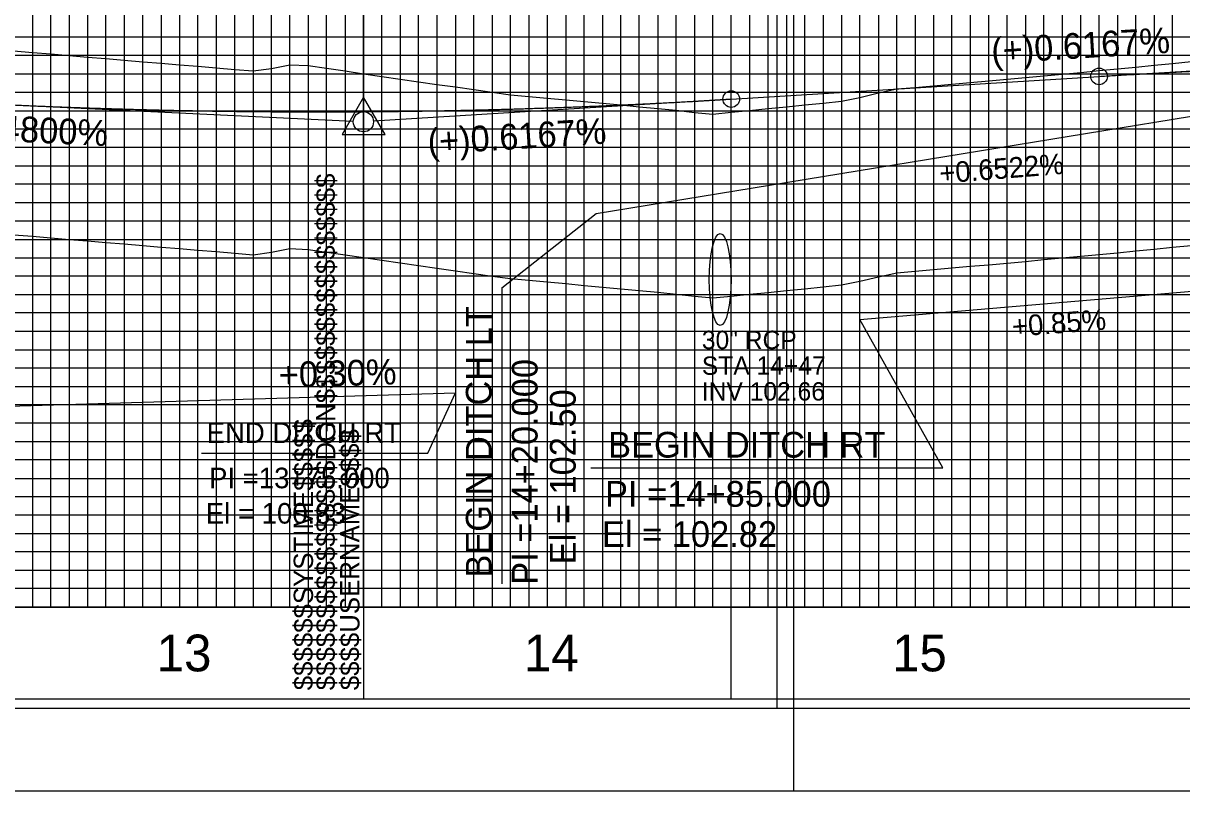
# Model space of a CAD drawing. Extents: x 2345490 to 2436403, y 465165 to 573888.
# Drawn here: x 2412152.8 to 2412467.8, y 527722 to 527930.9 of the extents above; entities that cross this region are included whole.
import ezdxf

# ---------------------------------------------------------------- set-up
doc = ezdxf.new("R2010")
doc.units = 0
for name, color, linetype in [('Old_Level_1', 7, 'Continuous'), ('Old_Level_18', 7, 'Continuous'), ('Old_Level_2', 7, 'Continuous'), ('Old_Level_3', 7, 'Continuous'), ('Old_Level_4', 7, 'Continuous'), ('Old_Level_40', 7, 'Continuous'), ('Old_Level_41', 7, 'Continuous'), ('Old_Level_42', 7, 'Continuous'), ('Old_Level_43', 7, 'Continuous'), ('Old_Level_50', 7, 'Continuous'), ('Old_Level_51', 7, 'Continuous'), ('Old_Level_61', 7, 'Continuous'), ('Old_Level_62', 7, 'Continuous'), ('Old_Level_63', 7, 'Continuous')]:
    doc.layers.add(name, color=color, linetype=linetype)

msp = doc.modelspace()

# ---------------------------------------------------------------- linework, layer by layer
at = {"layer": 'Old_Level_1'}
for points in [[(2412150.325, 527873.32075), (2412155.325, 527872.89975), (2412160.325, 527872.47925), (2412165.325, 527872.059), (2412170.325, 527871.63925), (2412175.325, 527871.22), (2412180.325, 527870.801), (2412185.325, 527870.38225), (2412190.325, 527869.964), (2412195.325, 527869.54625), (2412200.325, 527869.12875), (2412205.325, 527868.7115), (2412210.325, 527868.2945), (2412215.325, 527867.878), (2412220.325, 527868.54175), (2412225.325, 527869.5565), (2412230.325, 527869.31875), (2412235.325, 527868.58475), (2412240.325, 527867.85275), (2412245.325, 527867.1225), (2412250.325, 527866.39425), (2412255.325, 527865.66775), (2412260.325, 527864.94275), (2412265.325, 527864.21925), (2412270.325, 527863.49725), (2412275.325, 527862.77675), (2412280.325, 527862.0575), (2412285.325, 527861.40125), (2412290.325, 527860.93575), (2412295.325, 527860.47025), (2412300.325, 527860.00475), (2412305.325, 527859.5395), (2412310.325, 527859.0745), (2412315.325, 527858.6095), (2412320.325, 527858.1445), (2412325.325, 527857.6795), (2412330.325, 527857.18775), (2412335.325, 527856.59875), (2412340.325, 527856.11425), (2412345.325, 527856.617), (2412350.325, 527857.11975), (2412355.325, 527857.62275), (2412360.325, 527858.12575), (2412365.325, 527858.62925), (2412370.325, 527859.1335), (2412375.325, 527859.6385), (2412380.325, 527860.68375), (2412385.325, 527861.87775), (2412390.325, 527862.97175), (2412395.325, 527863.4045)], [(2412395.325, 527863.4045), (2412400.325, 527863.84), (2412405.325, 527864.27875), (2412410.325, 527864.721), (2412415.325, 527865.167), (2412420.325, 527865.61725), (2412425.325, 527866.07175), (2412430.325, 527866.53125), (2412435.325, 527866.99575), (2412440.325, 527867.4655), (2412445.325, 527867.94075), (2412450.325, 527868.42225), (2412455.325, 527868.91), (2412460.325, 527869.40425), (2412465.325, 527869.9055), (2412470.325, 527870.41375)]]:
    msp.add_lwpolyline(points, dxfattribs=at)
at = {"layer": 'Old_Level_18'}
msp.add_line((2412245.325, 527747.04275), (2412245.325, 527747.04275), dxfattribs=at)
msp.add_line((2412245.325, 527747.04275), (2412245.325, 527747.04275), dxfattribs=at)
for points in [[(2412345.325, 528797.04275), (2410845.325, 528797.04275), (2410845.325, 527747.04275), (2412345.325, 527747.04275)], [(2413745.325, 528797.04275), (2412245.325, 528797.04275), (2412245.325, 527747.04275), (2413745.325, 527747.04275)]]:
    msp.add_lwpolyline(points, close=True, dxfattribs=at)
at = {"layer": 'Old_Level_2'}
for p, q in [((2412445.325, 527916.3765), (2412542.58025, 527922.37375)), ((2412345.325, 527910.20975), (2412445.325, 527916.3765)), ((2412145.325, 527908.843), (2412242.57825, 527904.175)), ((2412345.325, 527910.20975), (2412248.07, 527904.2125))]:
    msp.add_line(p, q, dxfattribs=at)
msp.add_lwpolyline([(2412239.51925, 527900.592), (2412251.26175, 527900.592), (2412245.39075, 527910.71775)], close=True, dxfattribs=at)
for centre, radius in [((2412445.325, 527916.3765), 2.25), ((2412345.325, 527910.20975), 2.25), ((2412245.325, 527904.043), 2.75)]:
    msp.add_circle(centre, radius, dxfattribs=at)
for points in [[(2412445.325, 527916.3765), (2412449.325, 527916.61925), (2412453.325, 527916.85475), (2412457.325, 527917.0825), (2412461.325, 527917.303), (2412465.325, 527917.51575), (2412469.325, 527917.721), (2412473.325, 527917.91875), (2412477.325, 527918.109), (2412481.325, 527918.29175), (2412485.325, 527918.467), (2412489.325, 527918.63475), (2412493.325, 527918.79475), (2412497.325, 527918.9475), (2412501.325, 527919.0925), (2412505.325, 527919.23025), (2412509.325, 527919.36025), (2412513.325, 527919.48275), (2412517.325, 527919.59775), (2412521.325, 527919.70525), (2412525.325, 527919.80525), (2412529.325, 527919.89775), (2412533.325, 527919.98275), (2412537.325, 527920.06), (2412541.325, 527920.13), (2412545.325, 527920.19225), (2412549.325, 527920.24725), (2412553.325, 527920.2945), (2412557.325, 527920.33425), (2412561.325, 527920.3665), (2412565.325, 527920.39125), (2412569.325, 527920.4085), (2412573.325, 527920.41825), (2412577.325, 527920.4205), (2412581.325, 527920.41525), (2412585.325, 527920.40225), (2412589.325, 527920.382), (2412593.325, 527920.354), (2412597.325, 527920.3185), (2412601.325, 527920.27575), (2412605.325, 527920.22525), (2412609.325, 527920.16725), (2412613.325, 527920.10175), (2412617.325, 527920.02875), (2412621.325, 527919.948), (2412625.325, 527919.86), (2412629.325, 527919.7645), (2412633.325, 527919.66125), (2412637.325, 527919.55075), (2412641.325, 527919.4325), (2412645.325, 527919.30675)], [(2412145.325, 527908.843), (2412149.325, 527908.6555), (2412153.325, 527908.47675), (2412157.325, 527908.3065), (2412161.325, 527908.14525), (2412165.325, 527907.99275), (2412169.325, 527907.849), (2412173.325, 527907.714), (2412177.325, 527907.58775), (2412181.325, 527907.4705), (2412185.325, 527907.36175), (2412189.325, 527907.262), (2412193.325, 527907.17075), (2412197.325, 527907.0885), (2412201.325, 527907.015), (2412205.325, 527906.95), (2412209.325, 527906.894), (2412213.325, 527906.84675), (2412217.325, 527906.8085), (2412221.325, 527906.77875), (2412225.325, 527906.75775), (2412229.325, 527906.74575), (2412233.325, 527906.74225), (2412237.325, 527906.74775), (2412241.325, 527906.76175), (2412245.325, 527906.78475), (2412249.325, 527906.8165), (2412253.325, 527906.857), (2412257.325, 527906.90625), (2412261.325, 527906.96425), (2412265.325, 527907.031), (2412269.325, 527907.10675), (2412273.325, 527907.191), (2412277.325, 527907.28425), (2412281.325, 527907.386), (2412285.325, 527907.49675), (2412289.325, 527907.61625), (2412293.325, 527907.7445), (2412297.325, 527907.8815), (2412301.325, 527908.02725), (2412305.325, 527908.18175), (2412309.325, 527908.345), (2412313.325, 527908.51725), (2412317.325, 527908.698), (2412321.325, 527908.88775), (2412325.325, 527909.086), (2412329.325, 527909.29325), (2412333.325, 527909.50925), (2412337.325, 527909.734), (2412341.325, 527909.9675), (2412345.325, 527910.20975)]]:
    msp.add_spline(points, degree=3, dxfattribs=at)
at = {"layer": 'Old_Level_3'}
for p, q in [((2412308.63157, 527879.04516), (2412552.93924, 527919.02289)), ((2412282.97387, 527858.8775), (2412308.63157, 527879.04516)), ((2412282.97387, 527858.8775), (2412282.97387, 527778.33025)), ((2412380.325, 527850.24275), (2412495.325, 527860.04275)), ((2412402.87748, 527809.87907), (2412380.325, 527850.24275)), ((2411895.325, 527819.04275), (2412270.325, 527830.34275)), ((2412262.87798, 527813.9032), (2412270.325, 527830.34275)), ((2412201.33093, 527813.9032), (2412262.87798, 527813.9032)), ((2412307.11146, 527809.87907), (2412402.87748, 527809.87907))]:
    msp.add_line(p, q, dxfattribs=at)
at = {"layer": 'Old_Level_4'}
msp.add_ellipse((2412342.325, 527861.14275), major_axis=(0, 12.5), ratio=0.238746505, dxfattribs=at)
at = {"layer": 'Old_Level_40'}
msp.add_line((2412245.325, 527747.04275), (2412245.325, 527747.04275), dxfattribs=at)
msp.add_line((2412245.325, 527747.04275), (2412245.325, 527747.04275), dxfattribs=at)
msp.add_line((2412245.325, 527747.04275), (2412245.325, 527747.04275), dxfattribs=at)
msp.add_line((2412245.325, 527747.04275), (2412245.325, 527747.04275), dxfattribs=at)
at = {"layer": 'Old_Level_41'}
for p, q in [((2412345.325, 527772.04275), (2410845.325, 527772.04275)), ((2413745.325, 527772.04275), (2412245.325, 527772.04275))]:
    msp.add_line(p, q, dxfattribs=at)
for points in [[(2412295.325, 528797.04275), (2412295.325, 527772.04275), (2412345.325, 527772.04275), (2412345.325, 528797.04275)], [(2412320.325, 527772.04275), (2412320.325, 528797.04275)], [(2412370.325, 528797.04275), (2412370.325, 527772.04275), (2412420.325, 527772.04275), (2412420.325, 528797.04275)], [(2412395.325, 528797.04275), (2412395.325, 527772.04275), (2412445.325, 527772.04275), (2412445.325, 528797.04275)], [(2412170.325, 528659.49275), (2412170.325, 527772.04275), (2412220.325, 527772.04275), (2412220.325, 528659.49275)], [(2412270.325, 528659.49275), (2412270.325, 527772.04275)], [(2412345.325, 527897.04275), (2410845.325, 527897.04275), (2410845.325, 527847.04275), (2412345.325, 527847.04275)], [(2413745.325, 527897.04275), (2412245.325, 527897.04275), (2412245.325, 527847.04275), (2413745.325, 527847.04275)], [(2412345.325, 527822.04275), (2410845.325, 527822.04275), (2410845.325, 527872.04275), (2412345.325, 527872.04275)], [(2413745.325, 527822.04275), (2412245.325, 527822.04275), (2412245.325, 527872.04275), (2413745.325, 527872.04275)], [(2412345.325, 527797.04275), (2410845.325, 527797.04275)], [(2413745.325, 527797.04275), (2412245.325, 527797.04275)], [(2412282.825, 527747.04275), (2412282.825, 527747.04275)]]:
    msp.add_lwpolyline(points, dxfattribs=at)
at = {"layer": 'Old_Level_42'}
for points in [[(2412195.325, 528659.49275), (2412195.325, 527772.04275), (2412245.325, 527772.04275), (2412245.325, 528659.49275)], [(2412295.325, 528659.49275), (2412295.325, 527772.04275), (2412345.325, 527772.04275)], [(2412345.325, 527922.04275), (2410845.325, 527922.04275), (2410845.325, 527972.04275), (2412345.325, 527972.04275)], [(2413745.325, 527922.04275), (2412245.325, 527922.04275), (2412245.325, 527972.04275), (2413745.325, 527972.04275)]]:
    msp.add_lwpolyline(points, dxfattribs=at)
at = {"layer": 'Old_Level_43'}
for points in [[(2412300.325, 528797.04275), (2412300.325, 527772.04275), (2412305.325, 527772.04275), (2412305.325, 528797.04275)], [(2412310.325, 528797.04275), (2412310.325, 527772.04275), (2412315.325, 527772.04275), (2412315.325, 528797.04275)], [(2412325.325, 528797.04275), (2412325.325, 527772.04275), (2412330.325, 527772.04275), (2412330.325, 528797.04275)], [(2412335.325, 528797.04275), (2412335.325, 527772.04275), (2412340.325, 527772.04275), (2412340.325, 528797.04275)], [(2412350.325, 528797.04275), (2412350.325, 527772.04275), (2412355.325, 527772.04275), (2412355.325, 528797.04275)], [(2412360.325, 528797.04275), (2412360.325, 527772.04275), (2412365.325, 527772.04275), (2412365.325, 528797.04275)], [(2412375.325, 528797.04275), (2412375.325, 527772.04275), (2412380.325, 527772.04275), (2412380.325, 528797.04275)], [(2412385.325, 528797.04275), (2412385.325, 527772.04275), (2412390.325, 527772.04275), (2412390.325, 528797.04275)], [(2412400.325, 528797.04275), (2412400.325, 527772.04275), (2412405.325, 527772.04275), (2412405.325, 528797.04275)], [(2412410.325, 528797.04275), (2412410.325, 527772.04275), (2412415.325, 527772.04275), (2412415.325, 528797.04275)], [(2412425.325, 528797.04275), (2412425.325, 527772.04275), (2412430.325, 527772.04275), (2412430.325, 528797.04275)], [(2412435.325, 528797.04275), (2412435.325, 527772.04275), (2412440.325, 527772.04275), (2412440.325, 528797.04275)], [(2412450.325, 528797.04275), (2412450.325, 527772.04275), (2412455.325, 527772.04275), (2412455.325, 528797.04275)], [(2412460.325, 527772.04275), (2412465.325, 527772.04275), (2412465.325, 528797.04275)], [(2412460.325, 528797.04275), (2412460.325, 527772.04275)], [(2412155.325, 528659.49275), (2412155.325, 527772.04275), (2412160.325, 527772.04275), (2412160.325, 528659.49275)], [(2412165.325, 528659.49275), (2412165.325, 527772.04275), (2412175.325, 527772.04275), (2412175.325, 528659.49275)], [(2412180.325, 528659.49275), (2412180.325, 527772.04275), (2412185.325, 527772.04275), (2412185.325, 528659.49275)], [(2412190.325, 528659.49275), (2412190.325, 527772.04275), (2412200.325, 527772.04275), (2412200.325, 528659.49275)], [(2412205.325, 528659.49275), (2412205.325, 527772.04275), (2412210.325, 527772.04275), (2412210.325, 528659.49275)], [(2412215.325, 528659.49275), (2412215.325, 527772.04275), (2412225.325, 527772.04275), (2412225.325, 528659.49275)], [(2412230.325, 528659.49275), (2412230.325, 527772.04275)], [(2412230.325, 527772.04275), (2412235.325, 527772.04275), (2412235.325, 528659.49275)], [(2412240.325, 528659.49275), (2412240.325, 527772.04275), (2412250.325, 527772.04275), (2412250.325, 528659.49275)], [(2412255.325, 528659.49275), (2412255.325, 527772.04275), (2412260.325, 527772.04275), (2412260.325, 528659.49275)], [(2412265.325, 528659.49275), (2412265.325, 527772.04275), (2412275.325, 527772.04275), (2412275.325, 528659.49275)], [(2412280.325, 528659.49275), (2412280.325, 527772.04275), (2412285.325, 527772.04275), (2412285.325, 528659.49275)], [(2412290.325, 528659.49275), (2412290.325, 527772.04275), (2412300.325, 527772.04275)], [(2412295.325, 527927.04275), (2410895.325, 527927.04275), (2410895.325, 527917.04275), (2412295.325, 527917.04275)], [(2413695.325, 527927.04275), (2412295.325, 527927.04275), (2412295.325, 527917.04275), (2413695.325, 527917.04275)], [(2412295.325, 527912.04275), (2410895.325, 527912.04275), (2410895.325, 527907.04275), (2412295.325, 527907.04275)], [(2413695.325, 527912.04275), (2412295.325, 527912.04275), (2412295.325, 527907.04275), (2413695.325, 527907.04275)], [(2412295.325, 527902.04275), (2410895.325, 527902.04275), (2410895.325, 527892.04275), (2412295.325, 527892.04275)], [(2413695.325, 527902.04275), (2412295.325, 527902.04275), (2412295.325, 527892.04275), (2413695.325, 527892.04275)], [(2412295.325, 527887.04275), (2410895.325, 527887.04275), (2410895.325, 527882.04275), (2412295.325, 527882.04275)], [(2413695.325, 527887.04275), (2412295.325, 527887.04275), (2412295.325, 527882.04275), (2413695.325, 527882.04275)], [(2412295.325, 527877.04275), (2410895.325, 527877.04275), (2410895.325, 527867.04275), (2412295.325, 527867.04275)], [(2413695.325, 527877.04275), (2412295.325, 527877.04275), (2412295.325, 527867.04275), (2413695.325, 527867.04275)], [(2412295.325, 527862.04275), (2410895.325, 527862.04275), (2410895.325, 527857.04275), (2412295.325, 527857.04275)], [(2413695.325, 527862.04275), (2412295.325, 527862.04275), (2412295.325, 527857.04275), (2413695.325, 527857.04275)], [(2412295.325, 527852.04275), (2410895.325, 527852.04275), (2410895.325, 527842.04275), (2412295.325, 527842.04275)], [(2413695.325, 527852.04275), (2412295.325, 527852.04275), (2412295.325, 527842.04275), (2413695.325, 527842.04275)], [(2412295.325, 527837.04275), (2410895.325, 527837.04275), (2410895.325, 527832.04275), (2412295.325, 527832.04275)], [(2413695.325, 527837.04275), (2412295.325, 527837.04275), (2412295.325, 527832.04275), (2413695.325, 527832.04275)], [(2412295.325, 527827.04275), (2410895.325, 527827.04275), (2410895.325, 527817.04275), (2412295.325, 527817.04275)], [(2413695.325, 527827.04275), (2412295.325, 527827.04275), (2412295.325, 527817.04275), (2413695.325, 527817.04275)], [(2412295.325, 527812.04275), (2410895.325, 527812.04275), (2410895.325, 527807.04275), (2412295.325, 527807.04275)], [(2413695.325, 527812.04275), (2412295.325, 527812.04275), (2412295.325, 527807.04275), (2413695.325, 527807.04275)], [(2412295.325, 527802.04275), (2410895.325, 527802.04275), (2410895.325, 527792.04275), (2412295.325, 527792.04275)], [(2413695.325, 527802.04275), (2412295.325, 527802.04275), (2412295.325, 527792.04275), (2413695.325, 527792.04275)], [(2412295.325, 527787.04275), (2410895.325, 527787.04275), (2410895.325, 527782.04275), (2412295.325, 527782.04275)], [(2413695.325, 527787.04275), (2412295.325, 527787.04275), (2412295.325, 527782.04275), (2413695.325, 527782.04275)], [(2412295.325, 527777.04275), (2410895.325, 527777.04275)], [(2413695.325, 527777.04275), (2412295.325, 527777.04275)]]:
    msp.add_lwpolyline(points, dxfattribs=at)
at = {"layer": 'Old_Level_50'}
for points in [[(2412357.825, 528799.59275), (2410691.325, 528799.59275), (2410691.325, 527744.49275), (2412357.825, 527744.49275)], [(2413757.825, 528799.59275), (2412091.325, 528799.59275), (2412091.325, 527744.49275), (2413757.825, 527744.49275)]]:
    msp.add_lwpolyline(points, close=True, dxfattribs=at)
at = {"layer": 'Old_Level_51'}
for points in [[(2412362.325, 528822.04275), (2410678.325, 528822.04275), (2410678.325, 527722.04275), (2412362.325, 527722.04275)], [(2413762.325, 528822.04275), (2412078.325, 528822.04275), (2412078.325, 527722.04275), (2413762.325, 527722.04275)]]:
    msp.add_lwpolyline(points, close=True, dxfattribs=at)
at = {"layer": 'Old_Level_61'}
msp.add_lwpolyline([(2412395.325, 527913.4045), (2412400.325, 527913.84), (2412405.325, 527914.27875), (2412410.325, 527914.721), (2412415.325, 527915.167), (2412420.325, 527915.61725), (2412425.325, 527916.07175), (2412430.325, 527916.53125), (2412435.325, 527916.99575), (2412440.325, 527917.4655), (2412445.325, 527917.94075), (2412450.325, 527918.42225), (2412455.325, 527918.91), (2412460.325, 527919.40425), (2412465.325, 527919.9055), (2412470.325, 527920.41375)], dxfattribs=at)
at = {"layer": 'Old_Level_63'}
msp.add_line((2410895.325, 527772.04275), (2413081.64925, 527772.04275), dxfattribs=at)
msp.add_lwpolyline([(2412150.325, 527923.32075), (2412155.325, 527922.89975), (2412160.325, 527922.47925), (2412165.325, 527922.059), (2412170.325, 527921.63925), (2412175.325, 527921.22), (2412180.325, 527920.801), (2412185.325, 527920.38225), (2412190.325, 527919.964), (2412195.325, 527919.54625), (2412200.325, 527919.12875), (2412205.325, 527918.7115), (2412210.325, 527918.2945), (2412215.325, 527917.878), (2412220.325, 527918.54175), (2412225.325, 527919.5565), (2412230.325, 527919.31875), (2412235.325, 527918.58475), (2412240.325, 527917.85275), (2412245.325, 527917.1225), (2412250.325, 527916.39425), (2412255.325, 527915.66775), (2412260.325, 527914.94275), (2412265.325, 527914.21925), (2412270.325, 527913.49725), (2412275.325, 527912.77675), (2412280.325, 527912.0575), (2412285.325, 527911.40125), (2412290.325, 527910.93575), (2412295.325, 527910.47025), (2412300.325, 527910.00475), (2412305.325, 527909.5395), (2412310.325, 527909.0745), (2412315.325, 527908.6095), (2412320.325, 527908.1445), (2412325.325, 527907.6795), (2412330.325, 527907.18775), (2412335.325, 527906.59875), (2412340.325, 527906.11425), (2412345.325, 527906.617), (2412350.325, 527907.11975), (2412355.325, 527907.62275), (2412360.325, 527908.12575), (2412365.325, 527908.62925), (2412370.325, 527909.1335), (2412375.325, 527909.6385), (2412380.325, 527910.68375), (2412385.325, 527911.87775), (2412390.325, 527912.97175), (2412395.325, 527913.4045)], dxfattribs=at)

# ---------------------------------------------------------------- texts
at = {"layer": 'Old_Level_2'}
for s, rotation, p in [('(+)0.6167%', 3.5287722, (2412416.21385, 527919.80349)), ('(-)0.4800%', 357.2519111, (2412129.48175, 527899.61472)), ('(+)0.6167%', 3.5287722, (2412262.98325, 527895.113))]:
    msp.add_text(s, height=7.000001, rotation=rotation, dxfattribs=at).set_placement(p)
at = {"layer": 'Old_Level_3'}
for s, height, rotation, p in [('+0.6522%', 5.6, 4.5017741, (2412402.09415, 527887.21389)), ('BEGIN DITCH LT', 7.0000005, 90, (2412280.17619, 527780.03495)), ('+0.85%', 5.6, 4.5017741, (2412421.87671, 527845.52921)), ('30" RCP', 4.999999, 0.0000389, (2412337.34014, 527842.20544)), ('+0.30%', 7.000001, 1.7253956, (2412222.41706, 527831.64484)), ('STA 14+47', 4.999999, 0.0000389, (2412337.34014, 527835.20544)), ('PI =14+20.000', 7.0000005, 90, (2412292.67322, 527778.0948)), ('INV 102.66', 4.999999, 0.0000389, (2412337.34014, 527828.20544)), ('El = 102.50', 7.0000005, 90, (2412303.03929, 527783.65691)), ('END DITCH RT', 5.6000004, 360, (2412202.70397, 527816.64526)), ('BEGIN DITCH RT', 7.0000005, 360, (2412311.84382, 527812.68918)), ('PI =13+75.000', 5.6000004, 360, (2412203.35154, 527804.34847)), ('PI =14+85.000', 7.0000005, 360, (2412311.00842, 527799.31902)), ('El = 100.83', 5.6000004, 360, (2412202.46823, 527794.73412)), ('El = 102.82', 7.0000005, 360, (2412310.17302, 527788.39539))]:
    msp.add_text(s, height=height, rotation=rotation, dxfattribs=at).set_placement(p)
at = {"layer": 'Old_Level_41'}
for s, p in [('$$$$$$$$$$$$$$$$DGN$$$$$$$$$$$$$$$$', (2412237.675, 527749.40525)), ('$$$$$$SYSTIME$$$$$', (2412231.625, 527749.40525)), ('$$$$USERNAME$$$$', (2412244.25, 527749.41775))]:
    msp.add_text(s, height=5.25, rotation=90, dxfattribs=at).set_placement(p)
at = {"layer": 'Old_Level_62'}
for s, p in [('13', (2412189.131, 527754.543)), ('14', (2412288.9735, 527754.543)), ('15', (2412389.066, 527754.543))]:
    msp.add_text(s, height=10.000001, dxfattribs=at).set_placement(p)

doc.saveas('drawing.dxf')
